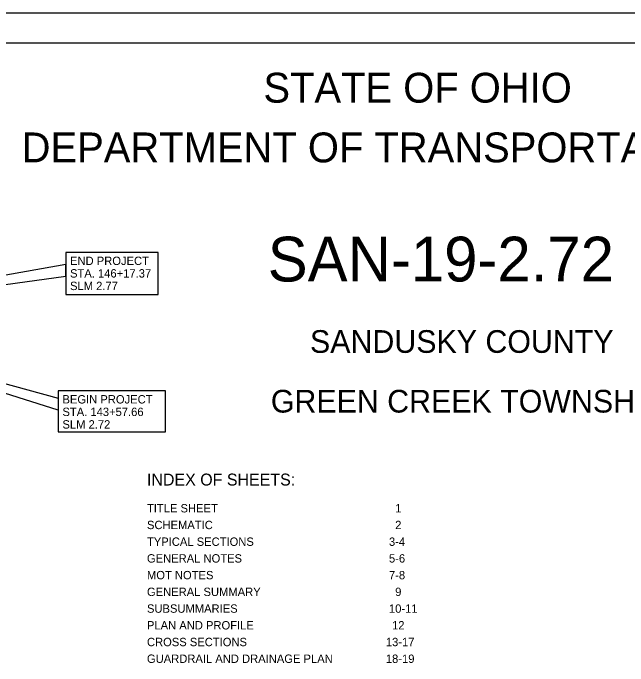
# Model space of a CAD drawing. Extents: x 36.7 to 70.7, y 0 to 22.
# Drawn here: x 46.3 to 56.59, y 11.06 to 22 of the extents above; entities that cross this region are included whole.
import ezdxf

# ---------------------------------------------------------------- set-up
doc = ezdxf.new("R2010")
doc.units = 0
for name, color, linetype in [('SH_Border', 7, 'Continuous'), ('SH_Cut_Line', 7, 'Continuous'), ('SH_Text', 7, 'Continuous')]:
    doc.layers.add(name, color=color, linetype=linetype)

msp = doc.modelspace()

# ---------------------------------------------------------------- linework, layer by layer
at = {"layer": 'SH_Border'}
msp.add_lwpolyline([(38.193, 21.497), (70.193, 21.497), (70.193, 0.497), (38.193, 0.497)], close=True, dxfattribs=at)
at = {"layer": 'SH_Cut_Line'}
msp.add_lwpolyline([(36.693, -0.003), (70.693, -0.003), (70.693, 21.997), (36.693, 21.997)], close=True, dxfattribs=at)
at = {"layer": 'SH_Text'}
for points in [[(47.18, 17.286), (48.727, 17.286), (48.727, 17.988), (47.18, 17.988)], [(47.18, 17.786), (42.243, 16.91), (47.18, 17.593)], [(42.251, 16.867), (47.053, 15.546), (47.053, 15.345)], [(47.053, 14.986), (48.847, 14.986), (48.847, 15.669), (47.053, 15.669)]]:
    msp.add_lwpolyline(points, close=True, dxfattribs=at)

# ---------------------------------------------------------------- texts
for s, height, p in [('STATE OF OHIO', 0.5, (50.488, 20.497)), ('DEPARTMENT OF TRANSPORTATION', 0.5, (46.44, 19.497)), ('SAN-19-2.72', 0.75, (50.56, 17.502)), ('END PROJECT', 0.14, (47.25, 17.778)), ('STA. 146+17.37', 0.14, (47.25, 17.568)), ('SLM 2.77', 0.14, (47.25, 17.358)), ('SANDUSKY COUNTY', 0.38, (51.268, 16.307)), ('GREEN CREEK TOWNSHIP', 0.38, (50.612, 15.307)), ('BEGIN PROJECT', 0.14, (47.123, 15.459)), ('STA. 143+57.66', 0.14, (47.123, 15.249)), ('SLM 2.72', 0.14, (47.123, 15.039)), ('INDEX OF SHEETS:', 0.2, (48.538, 14.085)), ('TITLE SHEET', 0.14, (48.538, 13.635)), ('   1', 0.14, (52.538, 13.635)), ('SCHEMATIC', 0.14, (48.538, 13.355)), ('   2', 0.14, (52.538, 13.355)), ('TYPICAL SECTIONS', 0.14, (48.538, 13.075)), (' 3-4', 0.14, (52.538, 13.075)), ('GENERAL NOTES', 0.14, (48.538, 12.795)), (' 5-6', 0.14, (52.538, 12.795)), ('MOT NOTES', 0.14, (48.538, 12.515)), (' 7-8', 0.14, (52.538, 12.515)), ('GENERAL SUMMARY', 0.14, (48.538, 12.235)), ('   9', 0.14, (52.538, 12.235)), ('SUBSUMMARIES', 0.14, (48.538, 11.955)), (' 10-11', 0.14, (52.538, 11.955)), ('PLAN AND PROFILE', 0.14, (48.538, 11.675)), ('  12', 0.14, (52.538, 11.675)), ('CROSS SECTIONS', 0.14, (48.538, 11.395)), ('13-17', 0.14, (52.538, 11.395)), ('GUARDRAIL AND DRAINAGE PLAN', 0.14, (48.538, 11.115)), ('18-19', 0.14, (52.538, 11.115))]:
    msp.add_text(s, height=height, dxfattribs=at).set_placement(p)

doc.saveas('drawing.dxf')
